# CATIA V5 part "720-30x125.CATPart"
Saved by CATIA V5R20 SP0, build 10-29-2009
Part number: 720-30x125
Definition: NONE
Nomenclature: 720-30x125
Source: Unknown
Description: 720-30x125
Bounding box of the stored display mesh (mm): x 0 to 125, y -15 to 15, z -15 to 15
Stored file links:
  C:\Users\Utente\Desktop\IO LAVORO\3D X SITO CF\X SITO\720\720-30x125.CATPart

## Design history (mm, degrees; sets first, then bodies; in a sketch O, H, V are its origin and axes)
Body1 "720-30x125" (main body)
  Solid1: solid without history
